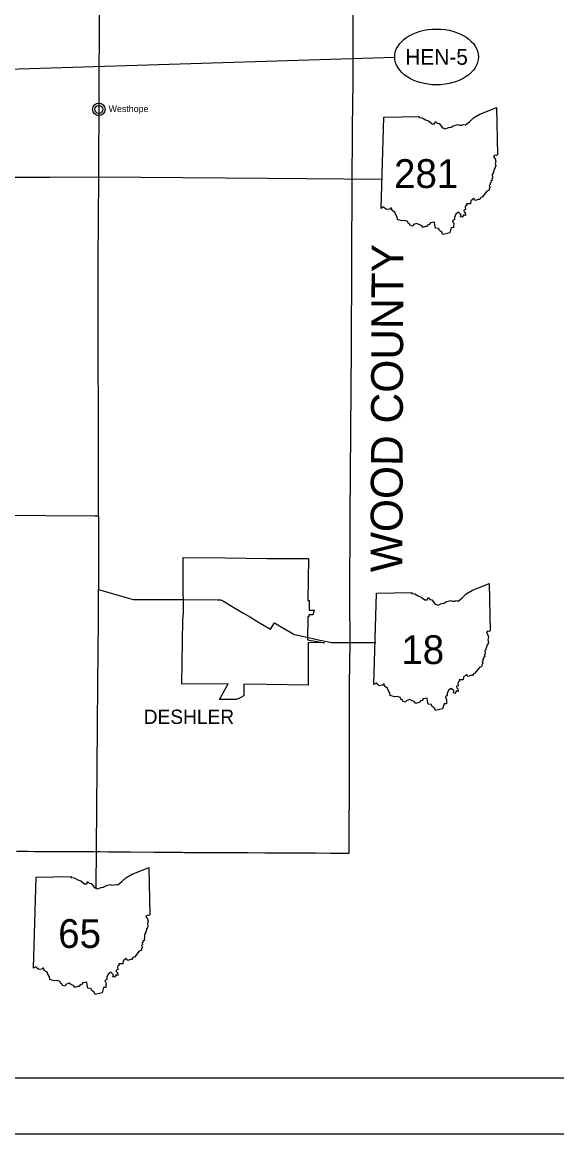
# Model space of a CAD drawing. Extents: x -62 to 810, y 0 to 440.
# Drawn here: x 421.2 to 517, y 0 to 199.3 of the extents above; entities that cross this region are included whole.
import ezdxf

# ---------------------------------------------------------------- set-up
doc = ezdxf.new("R2010")
doc.units = 0
for name, color, linetype in [('DV_X_Corp_Line', 7, 'Continuous'), ('GM_X_Adjacent_County_Text', 7, 'Continuous'), ('GM_X_Corporation_Text', 7, 'Continuous'), ('GM_X_County', 7, 'Continuous'), ('GM_X_State_Route', 7, 'Continuous'), ('PV_P_Text', 7, 'Continuous'), ('SH_Border', 7, 'Continuous'), ('SH_Cut_Line', 7, 'Continuous'), ('SH_Data', 7, 'Continuous')]:
    doc.layers.add(name, color=color, linetype=linetype)

msp = doc.modelspace()

# ---------------------------------------------------------------- linework, layer by layer
at = {"layer": 'DV_X_Corp_Line'}
msp.add_lwpolyline([(450.04, 103.34), (457.54, 103.26), (465.06, 103.18), (472.51, 103.13), (472.4, 95.63), (472.59, 95.63), (472.59, 93.91), (473.55, 93.92), (473.5, 93.83), (473.38, 93.52), (473.31, 93.21), (473.29, 93.04), (472.55, 93.04), (472.55, 92.7), (472.38, 92.7), (472.34, 88.6), (475.34, 88.01), (472.42, 88.08), (472.44, 80.46), (464.94, 80.55), (460.88, 80.61), (460.89, 78.55), (460.22, 78.17), (459.61, 77.87), (456.51, 77.87), (458.12, 80.66), (449.77, 80.65), (449.97, 92.1), (450.06, 93.45), (450.05, 99.29)], close=True, dxfattribs=at)
for radius in [1.12, 0.71]:
    msp.add_circle((434.9, 183.69), radius, dxfattribs=at)
at = {"layer": 'GM_X_County'}
msp.add_lwpolyline([(420.14, 50.65), (422.24, 50.65), (423.37, 50.64), (423.79, 50.63), (424.39, 50.63), (426.59, 50.62), (427.53, 50.61), (429.54, 50.6), (430.71, 50.6), (432.76, 50.59), (433.93, 50.59), (434.5, 50.58), (434.65, 50.59), (434.82, 50.59), (435.13, 50.59), (436.63, 50.58), (438.59, 50.57), (439.76, 50.56), (440.32, 50.56), (440.51, 50.56), (444.77, 50.52), (447.01, 50.5), (449.49, 50.48), (449.61, 50.48), (449.78, 50.47), (450.28, 50.46), (451.13, 50.45), (453, 50.44), (455.1, 50.44), (456.46, 50.44), (457.02, 50.44), (460.11, 50.43), (461.65, 50.42), (464.69, 50.4), (464.75, 50.4), (464.99, 50.39), (465.82, 50.39), (468.2, 50.38), (471.85, 50.36), (473.86, 50.35), (476.43, 50.33), (477.79, 50.32), (479.24, 50.31), (479.77, 50.3), (479.77, 50.89), (479.85, 65.33), (479.83, 72.97), (479.84, 80.57), (479.97, 88.07), (479.89, 95.66), (479.99, 110.74), (480.09, 125.92), (480.23, 140.95), (480.29, 156.05), (480.35, 171.24), (480.47, 186.28), (480.48, 186.82), (480.48, 201.49)], dxfattribs=at)
at = {"layer": 'GM_X_State_Route'}
for points in [[(434.91, 171.57), (434.91, 171.57), (434.96, 186.63), (434.96, 187.55), (435.02, 199.61), (435.02, 201.77), (435.08, 216.8), (435.25, 228.28), (435.32, 232.26)], [(359.43, 171.91), (374.49, 171.9), (387.05, 171.82), (389.68, 171.77), (399.71, 171.62), (404.47, 171.59), (413.64, 171.54), (419.66, 171.53), (426.12, 171.52), (434.91, 171.57)], [(434.85, 110.83), (434.84, 126.01), (434.83, 127.33), (434.76, 141.04), (434.81, 155.82), (434.81, 156.39), (434.82, 163.92), (434.91, 171.57)], [(434.91, 171.57), (449.96, 171.46), (465.17, 171.35), (485.68, 171.2)], [(407.72, 110.99), (434.19, 110.83), (434.85, 110.83)], [(434.85, 110.83), (434.86, 97.57)], [(434.45, 44.05), (434.63, 65.62), (434.74, 80.71), (434.82, 92.18), (434.85, 95.94), (434.86, 97.57)], [(434.86, 97.57), (439.83, 96.17), (441.06, 95.82), (450.05, 95.79)], [(450.05, 95.79), (456.16, 95.77), (456.48, 95.74), (456.7, 95.73), (456.9, 95.68), (457.05, 95.6), (457.28, 95.47), (457.35, 95.42), (457.41, 95.39), (457.55, 95.3)], [(457.55, 95.3), (458.51, 94.74), (459.69, 94.04), (460.86, 93.34), (462.08, 92.62), (463.26, 91.92), (463.32, 91.88), (463.41, 91.83)], [(463.41, 91.83), (465.71, 90.46)], [(465.71, 90.46), (466.4, 91.63)], [(466.4, 91.63), (467.61, 90.9), (468.75, 90.22)], [(468.75, 90.22), (468.78, 90.2), (468.82, 90.18), (469.75, 89.62), (469.97, 89.53), (470.03, 89.52), (470.33, 89.45), (472.46, 88.99)], [(472.46, 88.99), (472.51, 88.98), (474.54, 88.54)], [(474.54, 88.54), (475.85, 88.25), (476.32, 88.15), (476.58, 88.08), (476.76, 88.07), (484.56, 88.08)]]:
    msp.add_lwpolyline(points, dxfattribs=at)
at = {"layer": 'PV_P_Text'}
for p, q in [((485.53, 165.95), (485.99, 182.32)), ((485.53, 165.95), (485.99, 182.32)), ((484.23, 80.58), (484.69, 96.95)), ((484.23, 80.58), (484.69, 96.95)), ((423.18, 29.67), (423.64, 46.04)), ((423.18, 29.67), (423.64, 46.04))]:
    msp.add_line(p, q, dxfattribs=at)
for points in [[(485.99, 182.32), (492.34, 182.43), (492.25, 182.23), (492.85, 182.19), (493.48, 181.84), (494.02, 181.62), (494.68, 181.1), (495.07, 181.1), (495.24, 181.53), (495.54, 181.2), (495.9, 181.14), (496.52, 180.36), (497.03, 180.19), (497.64, 180.46), (498.1, 180.5), (498.43, 180.77), (499.31, 180.99), (499.55, 180.86), (500.01, 180.89), (500.24, 180.99), (500.65, 180.9), (501.35, 181.49), (502.08, 182.19), (503.21, 182.86), (504.88, 183.48), (506.21, 184.04), (506.4, 175.55)], [(485.99, 182.32), (492.34, 182.43), (492.25, 182.23), (492.85, 182.19), (493.48, 181.84), (494.02, 181.62), (494.68, 181.1), (495.07, 181.1), (495.24, 181.53), (495.54, 181.2), (495.9, 181.14), (496.52, 180.36), (497.03, 180.19), (497.64, 180.46), (498.1, 180.5), (498.43, 180.77), (499.31, 180.99), (499.55, 180.86), (500.01, 180.89), (500.24, 180.99), (500.65, 180.9), (501.35, 181.49), (502.08, 182.19), (503.21, 182.86), (504.88, 183.48), (506.21, 184.04), (506.4, 175.55)], [(506.4, 175.55), (506.2, 175.43), (505.9, 175.48), (505.69, 175.25), (505.95, 174.85), (506.07, 174.43), (505.96, 173.97), (506.07, 173.58), (505.99, 173.26), (505.8, 172.95), (505.74, 172.64), (505.57, 172.32), (505.59, 172.14), (505.43, 172), (505.46, 171.47), (505.38, 171.18), (505.41, 170.92), (505.16, 170.86), (505.22, 170.65), (505.06, 170.48), (505.09, 170.2), (504.91, 170.03), (505.08, 169.67), (504.94, 169.56), (504.83, 169.12), (504.5, 169.04), (503.86, 168.24), (503.63, 167.94), (503.37, 167.87), (503.23, 167.56), (502.92, 167.56), (502.44, 167.35), (502.13, 167.71), (501.59, 167.27), (501.53, 166.76), (500.84, 166.78), (500.87, 166.52), (500.72, 166.44), (500.58, 166.19), (500.66, 165.73), (500.34, 165.61), (500.38, 165.34), (500.58, 165.18), (500.67, 164.67), (500.33, 164.77), (500.06, 164.34), (499.77, 164.44), (499.86, 164.81), (499.38, 165.24), (498.92, 164.89), (498.68, 164.33), (498.68, 163.96), (498.34, 163.73), (498.56, 163.2), (498.52, 162.83), (498.52, 162.48), (498.1, 162.49), (497.84, 161.55)], [(506.4, 175.55), (506.2, 175.43), (505.9, 175.48), (505.69, 175.25), (505.95, 174.85), (506.07, 174.43), (505.96, 173.97), (506.07, 173.58), (505.99, 173.26), (505.8, 172.95), (505.74, 172.64), (505.57, 172.32), (505.59, 172.14), (505.43, 172), (505.46, 171.47), (505.38, 171.18), (505.41, 170.92), (505.16, 170.86), (505.22, 170.65), (505.06, 170.48), (505.09, 170.2), (504.91, 170.03), (505.08, 169.67), (504.94, 169.56), (504.83, 169.12), (504.5, 169.04), (503.86, 168.24), (503.63, 167.94), (503.37, 167.87), (503.23, 167.56), (502.92, 167.56), (502.44, 167.35), (502.13, 167.71), (501.59, 167.27), (501.53, 166.76), (500.84, 166.78), (500.87, 166.52), (500.72, 166.44), (500.58, 166.19), (500.66, 165.73), (500.34, 165.61), (500.38, 165.34), (500.58, 165.18), (500.67, 164.67), (500.33, 164.77), (500.06, 164.34), (499.77, 164.44), (499.86, 164.81), (499.38, 165.24), (498.92, 164.89), (498.68, 164.33), (498.68, 163.96), (498.34, 163.73), (498.56, 163.2), (498.52, 162.83), (498.52, 162.48), (498.1, 162.49), (497.84, 161.55)], [(497.84, 161.55), (497.1, 161.37), (496.58, 161.27), (496.4, 161.69), (496.03, 161.92), (495.79, 162.35), (495.27, 162.41), (495.14, 163), (495.08, 163.48), (494.36, 163.36), (494.16, 163.07), (493.91, 162.99), (493.76, 162.69), (493.41, 162.67), (493.03, 162.53), (492.79, 162.82), (492.17, 163.11), (491.9, 163.26), (491.32, 163.03), (491.2, 162.75), (490.74, 162.87), (490.63, 163.18), (490.35, 163.27), (490.29, 163.6), (489.69, 163.77), (489.24, 163.7), (488.44, 163.96), (488.39, 164.39), (488.12, 164.92), (487.97, 165.28), (487.47, 165.56), (487.36, 165.99), (487.2, 165.97), (487.05, 165.8), (486.49, 165.72), (486.27, 165.9), (485.95, 166.2), (485.53, 165.95)], [(497.84, 161.55), (497.1, 161.37), (496.58, 161.27), (496.4, 161.69), (496.03, 161.92), (495.79, 162.35), (495.27, 162.41), (495.14, 163), (495.08, 163.48), (494.36, 163.36), (494.16, 163.07), (493.91, 162.99), (493.76, 162.69), (493.41, 162.67), (493.03, 162.53), (492.79, 162.82), (492.17, 163.11), (491.9, 163.26), (491.32, 163.03), (491.2, 162.75), (490.74, 162.87), (490.63, 163.18), (490.35, 163.27), (490.29, 163.6), (489.69, 163.77), (489.24, 163.7), (488.44, 163.96), (488.39, 164.39), (488.12, 164.92), (487.97, 165.28), (487.47, 165.56), (487.36, 165.99), (487.2, 165.97), (487.05, 165.8), (486.49, 165.72), (486.27, 165.9), (485.95, 166.2), (485.53, 165.95)], [(484.69, 96.95), (491.04, 97.06), (490.94, 96.86), (491.54, 96.82), (492.18, 96.47), (492.72, 96.25), (493.38, 95.73), (493.77, 95.73), (493.94, 96.16), (494.24, 95.83), (494.6, 95.77), (495.22, 94.99), (495.73, 94.82), (496.34, 95.09), (496.8, 95.13), (497.13, 95.4), (498, 95.62), (498.25, 95.49), (498.71, 95.51), (498.94, 95.61), (499.34, 95.52), (500.05, 96.12), (500.78, 96.82), (501.9, 97.48), (503.58, 98.11), (504.9, 98.67), (505.1, 90.18)], [(484.69, 96.95), (491.04, 97.06), (490.94, 96.86), (491.54, 96.82), (492.18, 96.47), (492.72, 96.25), (493.38, 95.73), (493.77, 95.73), (493.94, 96.16), (494.24, 95.83), (494.6, 95.77), (495.22, 94.99), (495.73, 94.82), (496.34, 95.09), (496.8, 95.13), (497.13, 95.4), (498, 95.62), (498.25, 95.49), (498.71, 95.51), (498.94, 95.61), (499.34, 95.52), (500.05, 96.12), (500.78, 96.82), (501.9, 97.48), (503.58, 98.11), (504.9, 98.67), (505.1, 90.18)], [(505.1, 90.18), (504.9, 90.06), (504.6, 90.11), (504.39, 89.87), (504.64, 89.48), (504.76, 89.06), (504.66, 88.59), (504.76, 88.21), (504.69, 87.89), (504.5, 87.57), (504.43, 87.27), (504.27, 86.95), (504.29, 86.77), (504.13, 86.63), (504.16, 86.1), (504.08, 85.81), (504.11, 85.55), (503.86, 85.48), (503.91, 85.27), (503.75, 85.11), (503.79, 84.83), (503.61, 84.66), (503.78, 84.3), (503.64, 84.19), (503.52, 83.75), (503.2, 83.66), (502.55, 82.87), (502.33, 82.57), (502.07, 82.5), (501.93, 82.19), (501.61, 82.19), (501.14, 81.98), (500.83, 82.34), (500.29, 81.9), (500.23, 81.39), (499.54, 81.41), (499.57, 81.15), (499.42, 81.07), (499.28, 80.81), (499.36, 80.35), (499.04, 80.24), (499.08, 79.97), (499.28, 79.81), (499.37, 79.3), (499.03, 79.4), (498.75, 78.97), (498.47, 79.07), (498.56, 79.44), (498.08, 79.87), (497.62, 79.52), (497.38, 78.96), (497.38, 78.59), (497.04, 78.36), (497.26, 77.83), (497.22, 77.46), (497.22, 77.11), (496.8, 77.12), (496.54, 76.18)], [(505.1, 90.18), (504.9, 90.06), (504.6, 90.11), (504.39, 89.87), (504.64, 89.48), (504.76, 89.06), (504.66, 88.59), (504.76, 88.21), (504.69, 87.89), (504.5, 87.57), (504.43, 87.27), (504.27, 86.95), (504.29, 86.77), (504.13, 86.63), (504.16, 86.1), (504.08, 85.81), (504.11, 85.55), (503.86, 85.48), (503.91, 85.27), (503.75, 85.11), (503.79, 84.83), (503.61, 84.66), (503.78, 84.3), (503.64, 84.19), (503.52, 83.75), (503.2, 83.66), (502.55, 82.87), (502.33, 82.57), (502.07, 82.5), (501.93, 82.19), (501.61, 82.19), (501.14, 81.98), (500.83, 82.34), (500.29, 81.9), (500.23, 81.39), (499.54, 81.41), (499.57, 81.15), (499.42, 81.07), (499.28, 80.81), (499.36, 80.35), (499.04, 80.24), (499.08, 79.97), (499.28, 79.81), (499.37, 79.3), (499.03, 79.4), (498.75, 78.97), (498.47, 79.07), (498.56, 79.44), (498.08, 79.87), (497.62, 79.52), (497.38, 78.96), (497.38, 78.59), (497.04, 78.36), (497.26, 77.83), (497.22, 77.46), (497.22, 77.11), (496.8, 77.12), (496.54, 76.18)], [(496.54, 76.18), (495.8, 76), (495.28, 75.9), (495.1, 76.32), (494.73, 76.55), (494.49, 76.98), (493.96, 77.04), (493.84, 77.63), (493.78, 78.11), (493.06, 77.99), (492.86, 77.69), (492.6, 77.62), (492.45, 77.32), (492.1, 77.3), (491.73, 77.16), (491.48, 77.45), (490.87, 77.74), (490.59, 77.89), (490.02, 77.65), (489.89, 77.38), (489.43, 77.5), (489.33, 77.81), (489.05, 77.9), (488.99, 78.23), (488.39, 78.4), (487.94, 78.33), (487.14, 78.59), (487.09, 79.02), (486.81, 79.54), (486.67, 79.91), (486.16, 80.19), (486.06, 80.62), (485.9, 80.6), (485.75, 80.43), (485.19, 80.35), (484.96, 80.53), (484.65, 80.83), (484.23, 80.58)], [(496.54, 76.18), (495.8, 76), (495.28, 75.9), (495.1, 76.32), (494.73, 76.55), (494.49, 76.98), (493.96, 77.04), (493.84, 77.63), (493.78, 78.11), (493.06, 77.99), (492.86, 77.69), (492.6, 77.62), (492.45, 77.32), (492.1, 77.3), (491.73, 77.16), (491.48, 77.45), (490.87, 77.74), (490.59, 77.89), (490.02, 77.65), (489.89, 77.38), (489.43, 77.5), (489.33, 77.81), (489.05, 77.9), (488.99, 78.23), (488.39, 78.4), (487.94, 78.33), (487.14, 78.59), (487.09, 79.02), (486.81, 79.54), (486.67, 79.91), (486.16, 80.19), (486.06, 80.62), (485.9, 80.6), (485.75, 80.43), (485.19, 80.35), (484.96, 80.53), (484.65, 80.83), (484.23, 80.58)], [(423.64, 46.04), (429.99, 46.15), (429.89, 45.95), (430.49, 45.91), (431.13, 45.56), (431.67, 45.34), (432.33, 44.82), (432.72, 44.83), (432.89, 45.25), (433.19, 44.92), (433.55, 44.86), (434.17, 44.08), (434.68, 43.91), (435.29, 44.18), (435.75, 44.22), (436.08, 44.49), (436.96, 44.72), (437.2, 44.58), (437.66, 44.61), (437.89, 44.71), (438.29, 44.62), (439, 45.21), (439.73, 45.92), (440.85, 46.58), (442.53, 47.21), (443.86, 47.77), (444.05, 39.27)], [(423.64, 46.04), (429.99, 46.15), (429.89, 45.95), (430.49, 45.91), (431.13, 45.56), (431.67, 45.34), (432.33, 44.82), (432.72, 44.83), (432.89, 45.25), (433.19, 44.92), (433.55, 44.86), (434.17, 44.08), (434.68, 43.91), (435.29, 44.18), (435.75, 44.22), (436.08, 44.49), (436.96, 44.72), (437.2, 44.58), (437.66, 44.61), (437.89, 44.71), (438.29, 44.62), (439, 45.21), (439.73, 45.92), (440.85, 46.58), (442.53, 47.21), (443.86, 47.77), (444.05, 39.27)], [(444.05, 39.27), (443.85, 39.15), (443.55, 39.21), (443.34, 38.97), (443.6, 38.57), (443.72, 38.15), (443.61, 37.69), (443.71, 37.31), (443.64, 36.99), (443.45, 36.67), (443.39, 36.36), (443.22, 36.05), (443.24, 35.87), (443.08, 35.72), (443.11, 35.19), (443.03, 34.9), (443.06, 34.64), (442.81, 34.58), (442.86, 34.37), (442.7, 34.21), (442.74, 33.93), (442.56, 33.75), (442.73, 33.39), (442.59, 33.28), (442.47, 32.85), (442.15, 32.76), (441.51, 31.97), (441.28, 31.67), (441.02, 31.59), (440.88, 31.28), (440.56, 31.28), (440.09, 31.07), (439.78, 31.44), (439.24, 30.99), (439.18, 30.48), (438.49, 30.5), (438.52, 30.24), (438.37, 30.17), (438.23, 29.91), (438.31, 29.45), (437.99, 29.33), (438.03, 29.06), (438.23, 28.9), (438.32, 28.39), (437.98, 28.49), (437.7, 28.06), (437.42, 28.17), (437.51, 28.53), (437.03, 28.97), (436.57, 28.62), (436.33, 28.06), (436.33, 27.68), (435.99, 27.45), (436.21, 26.92), (436.17, 26.55), (436.17, 26.2), (435.75, 26.22), (435.49, 25.28)], [(444.05, 39.27), (443.85, 39.15), (443.55, 39.21), (443.34, 38.97), (443.6, 38.57), (443.72, 38.15), (443.61, 37.69), (443.71, 37.31), (443.64, 36.99), (443.45, 36.67), (443.39, 36.36), (443.22, 36.05), (443.24, 35.87), (443.08, 35.72), (443.11, 35.19), (443.03, 34.9), (443.06, 34.64), (442.81, 34.58), (442.86, 34.37), (442.7, 34.21), (442.74, 33.93), (442.56, 33.75), (442.73, 33.39), (442.59, 33.28), (442.47, 32.85), (442.15, 32.76), (441.51, 31.97), (441.28, 31.67), (441.02, 31.59), (440.88, 31.28), (440.56, 31.28), (440.09, 31.07), (439.78, 31.44), (439.24, 30.99), (439.18, 30.48), (438.49, 30.5), (438.52, 30.24), (438.37, 30.17), (438.23, 29.91), (438.31, 29.45), (437.99, 29.33), (438.03, 29.06), (438.23, 28.9), (438.32, 28.39), (437.98, 28.49), (437.7, 28.06), (437.42, 28.17), (437.51, 28.53), (437.03, 28.97), (436.57, 28.62), (436.33, 28.06), (436.33, 27.68), (435.99, 27.45), (436.21, 26.92), (436.17, 26.55), (436.17, 26.2), (435.75, 26.22), (435.49, 25.28)], [(435.49, 25.28), (434.75, 25.1), (434.23, 24.99), (434.05, 25.42), (433.68, 25.64), (433.44, 26.07), (432.91, 26.13), (432.79, 26.72), (432.73, 27.2), (432.01, 27.08), (431.81, 26.79), (431.55, 26.71), (431.4, 26.41), (431.06, 26.39), (430.68, 26.25), (430.44, 26.54), (429.82, 26.83), (429.55, 26.98), (428.97, 26.75), (428.84, 26.47), (428.38, 26.59), (428.28, 26.9), (428, 26.99), (427.94, 27.32), (427.34, 27.49), (426.89, 27.42), (426.09, 27.69), (426.04, 28.12), (425.76, 28.64), (425.62, 29), (425.12, 29.28), (425.01, 29.71), (424.85, 29.7), (424.7, 29.52), (424.14, 29.44), (423.91, 29.62), (423.6, 29.92), (423.18, 29.67)], [(435.49, 25.28), (434.75, 25.1), (434.23, 24.99), (434.05, 25.42), (433.68, 25.64), (433.44, 26.07), (432.91, 26.13), (432.79, 26.72), (432.73, 27.2), (432.01, 27.08), (431.81, 26.79), (431.55, 26.71), (431.4, 26.41), (431.06, 26.39), (430.68, 26.25), (430.44, 26.54), (429.82, 26.83), (429.55, 26.98), (428.97, 26.75), (428.84, 26.47), (428.38, 26.59), (428.28, 26.9), (428, 26.99), (427.94, 27.32), (427.34, 27.49), (426.89, 27.42), (426.09, 27.69), (426.04, 28.12), (425.76, 28.64), (425.62, 29), (425.12, 29.28), (425.01, 29.71), (424.85, 29.7), (424.7, 29.52), (424.14, 29.44), (423.91, 29.62), (423.6, 29.92), (423.18, 29.67)]]:
    msp.add_lwpolyline(points, dxfattribs=at)
at = {"layer": 'SH_Border'}
msp.add_lwpolyline([(30, 430), (670, 430), (670, 10), (30, 10)], close=True, dxfattribs=at)
at = {"layer": 'SH_Cut_Line'}
msp.add_lwpolyline([(0, 0), (680, 0), (680, 440), (0, 440)], close=True, dxfattribs=at)
at = {"layer": 'SH_Data'}
msp.add_line((487.96, 193), (360.28, 189.02), dxfattribs=at)
msp.add_ellipse((495.46, 193.1), major_axis=(7.5, 0), ratio=0.666667, dxfattribs=at)

# ---------------------------------------------------------------- texts
at = {"layer": 'GM_X_Adjacent_County_Text'}
msp.add_text('WOOD COUNTY', height=5.7, rotation=89.8081, dxfattribs=at).set_placement((489.32, 100.69))
at = {"layer": 'GM_X_Corporation_Text'}
for s, height, p in [('Westhope', 1.188, (436.65, 183.21)), ('DESHLER', 2.565, (442.95, 73.49))]:
    msp.add_text(s, height=height, rotation=0, dxfattribs=at).set_placement(p)
at = {"layer": 'PV_P_Text'}
for s, p in [('281', (487.84, 169.6)), ('18', (489.14, 84.23)), ('65', (427.61, 33.32))]:
    msp.add_text(s, height=5.162, dxfattribs=at).set_placement(p)
at = {"layer": 'SH_Data'}
msp.add_text('HEN-5', height=2.8, dxfattribs=at).set_placement((489.84, 191.7))

doc.saveas('drawing.dxf')
